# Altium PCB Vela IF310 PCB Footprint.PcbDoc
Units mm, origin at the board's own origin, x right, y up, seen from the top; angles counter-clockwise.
Board outline 12 x 16 mm, 2 copper layers (Top Layer, Bottom Layer); 1 components, 0 nets, 84 pads, 0 vias.
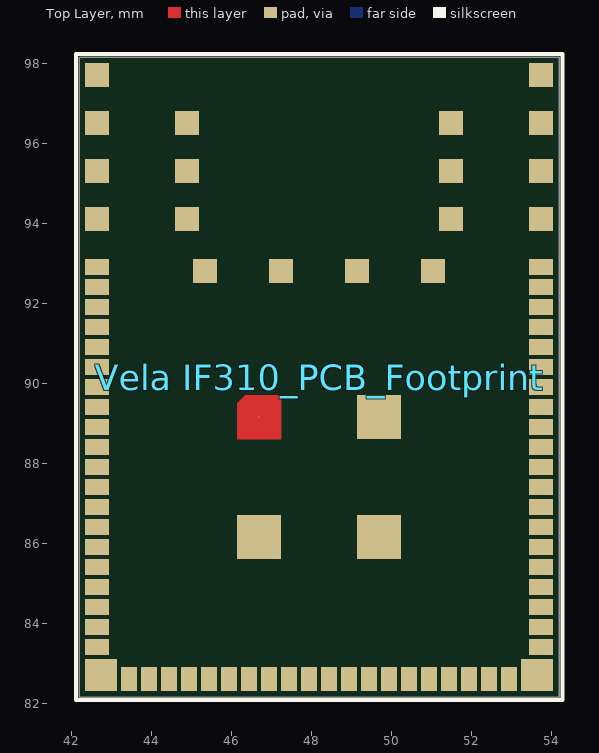
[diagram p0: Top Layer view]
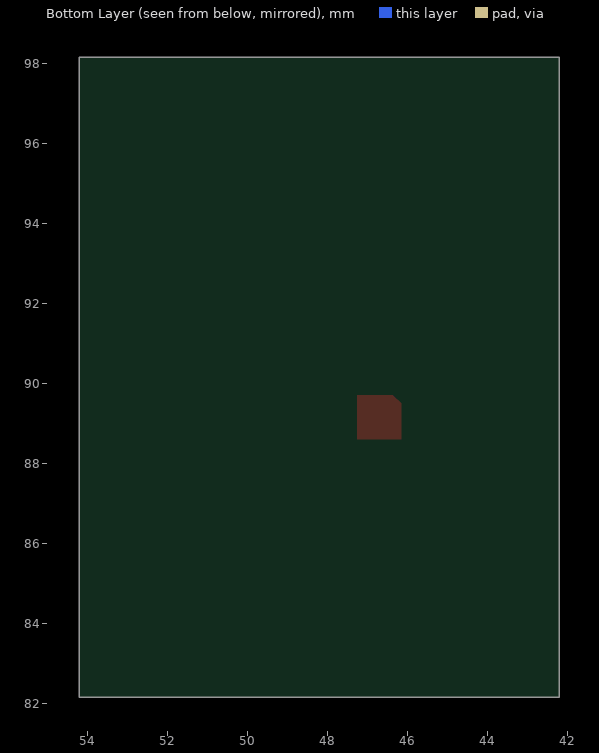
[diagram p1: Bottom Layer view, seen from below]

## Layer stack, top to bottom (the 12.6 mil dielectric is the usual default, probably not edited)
Top Solder: solder mask 0.0102, Solder Resist, Dk 3.5
Top Layer: signal copper 0.0356
Dielectric 1: dielectric 0.32, FR-4, Dk 4.8
Bottom Layer: signal copper 0.0356
Bottom Solder: solder mask 0.0102, Solder Resist, Dk 3.5

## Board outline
42.203,82.165 42.203,98.165 54.203,98.165 54.203,82.165

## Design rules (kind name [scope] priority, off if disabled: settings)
Clearance [All] p1: gap=0.254 ignorepadtopadclearanceinfootprint=FALSE
PolygonConnect [All] p1: connectstyle=Relief reliefconductorwidth=0.254 reliefentries=4 polygonreliefangle="90 Angle" airgapwidth=0.254
RoutingVias [All] p1: holewidth=0.711 width=1.27 viastyle="Through Hole" minholewidth=0.711 minwidth=1.27 maxholewidth=0.711 maxwidth=1.27
SolderMaskExpansion [All] p1: expansion=0.102 istentingtop=FALSE
Width [All] p1: maxlimit=0.254 minlimit=0.254 preferedwidth=0.254
30 further rules are at their usual default settings.

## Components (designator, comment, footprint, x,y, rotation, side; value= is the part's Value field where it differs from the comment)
"Vela IF310_PCB_Footprint" "Comment" "Ezurio, Vela IF310 Module, Platform Side" 48.203,90.165 r0 top

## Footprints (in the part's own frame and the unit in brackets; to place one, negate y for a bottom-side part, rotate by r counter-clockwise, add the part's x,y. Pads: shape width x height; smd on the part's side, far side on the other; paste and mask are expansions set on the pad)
"Ezurio, Vela IF310 Module, Platform Side" [mm] "Ezurio, Vela IF310 Module, Platform Side"
  rect 0.6x0.4 smd paste-0.05 mask-0.05: 1(-5.55,2.75) 2(-5.55,2.25) 3(-5.55,1.75) 4(-5.55,1.25) 5(-5.55,0.75) 6(-5.55,0.25) 7(-5.55,-0.25) 8(-5.55,-0.75) 9(-5.55,-1.25) 10(-5.55,-1.75) 11(-5.55,-2.25) 12(-5.55,-2.75) 13(-5.55,-3.25) 14(-5.55,-3.75) 15(-5.55,-4.25) 16(-5.55,-4.75) 17(-5.55,-5.25) 18(-5.55,-5.75) 19(-5.55,-6.25) 20(-5.55,-6.75) 41(5.55,-6.75) 42(5.55,-6.25) 43(5.55,-5.75) 44(5.55,-5.25) 45(5.55,-4.75) 46(5.55,-4.25) 47(5.55,-3.75) 48(5.55,-3.25) 49(5.55,-2.75) 50(5.55,-2.25) 51(5.55,-1.75) 52(5.55,-1.25) 53(5.55,-0.75) 54(5.55,-0.25) 55(5.55,0.25) 56(5.55,0.75) 57(5.55,1.25) 58(5.55,1.75) 59(5.55,2.25) 60(5.55,2.75)
  rect 0.4x0.6 smd paste-0.05 mask-0.05: 21(-4.75,-7.55) 22(-4.25,-7.55) 23(-3.75,-7.55) 24(-3.25,-7.55) 25(-2.75,-7.55) 26(-2.25,-7.55) 27(-1.75,-7.55) 28(-1.25,-7.55) 29(-0.75,-7.55) 30(-0.25,-7.55) 31(0.25,-7.55) 32(0.75,-7.55) 33(1.25,-7.55) 34(1.75,-7.55) 35(2.25,-7.55) 36(2.75,-7.55) 37(3.25,-7.55) 38(3.75,-7.55) 39(4.25,-7.55) 40(4.75,-7.55)
  rrect0% 0.6x0.6 smd paste-0.05 mask-0.05: 61(5.55,3.95) 62(5.55,5.15) 63(5.55,6.35) 64(5.55,7.55) 65(3.3,3.95) 66(3.3,5.15) 67(3.3,6.35) 68(-3.3,3.95) 69(-3.3,5.15) 70(-3.3,6.35) 71(-5.55,3.95) 72(-5.55,5.15) 73(-5.55,6.35) 74(-5.55,7.55)
  rect 0.6x0.6 smd paste-0.05 mask-0.05: 75(-2.85,2.65) 76(-0.95,2.65) 77(0.95,2.65) 78(2.85,2.65)
  rect 0.8x0.8 smd paste-0.05 mask-0.05: 79(-5.45,-7.45) 80(5.45,-7.45)
  round 0.025 smd paste-0.05 mask-0.05: G1(-1.5,-1)
  rect 1.1x1.1 smd paste-0.05 mask-0.05: G2(-1.5,-4) G3(1.5,-4) G4(1.5,-1)
  Top Layer region: -1.845,-0.45 -2.05,-0.655 -2.05,-0.655 -2.05,-1.55 -0.95,-1.55 -0.95,-0.45
  silkscreen extent -6.08,-8.08 6.08,8.08, body extent -5.8,-7.8 5.8,7.8, height 0.01

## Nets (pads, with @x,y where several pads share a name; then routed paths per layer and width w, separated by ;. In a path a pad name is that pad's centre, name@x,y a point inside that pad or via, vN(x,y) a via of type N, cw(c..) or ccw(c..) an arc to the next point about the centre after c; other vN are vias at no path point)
pads on no net: "Vela IF310_PCB_Footprint.1" "Vela IF310_PCB_Footprint.2" "Vela IF310_PCB_Footprint.3" "Vela IF310_PCB_Footprint.4" "Vela IF310_PCB_Footprint.5" "Vela IF310_PCB_Footprint.6" "Vela IF310_PCB_Footprint.7" "Vela IF310_PCB_Footprint.8" "Vela IF310_PCB_Footprint.9" "Vela IF310_PCB_Footprint.10" "Vela IF310_PCB_Footprint.11" "Vela IF310_PCB_Footprint.12" "Vela IF310_PCB_Footprint.13" "Vela IF310_PCB_Footprint.14" "Vela IF310_PCB_Footprint.15" "Vela IF310_PCB_Footprint.16" "Vela IF310_PCB_Footprint.17" "Vela IF310_PCB_Footprint.18" "Vela IF310_PCB_Footprint.19" "Vela IF310_PCB_Footprint.20" "Vela IF310_PCB_Footprint.21" "Vela IF310_PCB_Footprint.22" "Vela IF310_PCB_Footprint.23" "Vela IF310_PCB_Footprint.24" "Vela IF310_PCB_Footprint.25" "Vela IF310_PCB_Footprint.26" "Vela IF310_PCB_Footprint.27" "Vela IF310_PCB_Footprint.28" "Vela IF310_PCB_Footprint.29" "Vela IF310_PCB_Footprint.30" "Vela IF310_PCB_Footprint.31" "Vela IF310_PCB_Footprint.32" "Vela IF310_PCB_Footprint.33" "Vela IF310_PCB_Footprint.34" "Vela IF310_PCB_Footprint.35" "Vela IF310_PCB_Footprint.36" "Vela IF310_PCB_Footprint.37" "Vela IF310_PCB_Footprint.38" "Vela IF310_PCB_Footprint.39" "Vela IF310_PCB_Footprint.40" "Vela IF310_PCB_Footprint.41" "Vela IF310_PCB_Footprint.42" "Vela IF310_PCB_Footprint.43" "Vela IF310_PCB_Footprint.44" "Vela IF310_PCB_Footprint.45" "Vela IF310_PCB_Footprint.46" "Vela IF310_PCB_Footprint.47" "Vela IF310_PCB_Footprint.48" "Vela IF310_PCB_Footprint.49" "Vela IF310_PCB_Footprint.50" "Vela IF310_PCB_Footprint.51" "Vela IF310_PCB_Footprint.52" "Vela IF310_PCB_Footprint.53" "Vela IF310_PCB_Footprint.54" "Vela IF310_PCB_Footprint.55" "Vela IF310_PCB_Footprint.56" "Vela IF310_PCB_Footprint.57" "Vela IF310_PCB_Footprint.58" "Vela IF310_PCB_Footprint.59" "Vela IF310_PCB_Footprint.60" "Vela IF310_PCB_Footprint.61" "Vela IF310_PCB_Footprint.62" "Vela IF310_PCB_Footprint.63" "Vela IF310_PCB_Footprint.64" "Vela IF310_PCB_Footprint.65" "Vela IF310_PCB_Footprint.66" "Vela IF310_PCB_Footprint.67" "Vela IF310_PCB_Footprint.68" "Vela IF310_PCB_Footprint.69" "Vela IF310_PCB_Footprint.70" "Vela IF310_PCB_Footprint.71" "Vela IF310_PCB_Footprint.72" "Vela IF310_PCB_Footprint.73" "Vela IF310_PCB_Footprint.74" "Vela IF310_PCB_Footprint.75" "Vela IF310_PCB_Footprint.76" "Vela IF310_PCB_Footprint.77" "Vela IF310_PCB_Footprint.78" "Vela IF310_PCB_Footprint.79" "Vela IF310_PCB_Footprint.80" "Vela IF310_PCB_Footprint.G1" "Vela IF310_PCB_Footprint.G2" "Vela IF310_PCB_Footprint.G3" "Vela IF310_PCB_Footprint.G4"

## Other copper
Top Layer:
  pour cut-out: 44.403,98.165 44.403,97.065 45.203,97.065 45.203,93.165 51.203,93.165 51.203,97.065 51.803,97.065 51.803,96.371 53.072,96.371 53.072,98.165
Bottom Layer:
  pour cut-out: 44.403,98.165 44.403,97.065 45.203,97.065 45.203,93.165 51.203,93.165 51.203,97.065 51.803,97.065 51.803,96.371 53.072,96.371 53.072,98.165

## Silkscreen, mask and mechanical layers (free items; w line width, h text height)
Board Outline:
  the board outline again, w0.025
